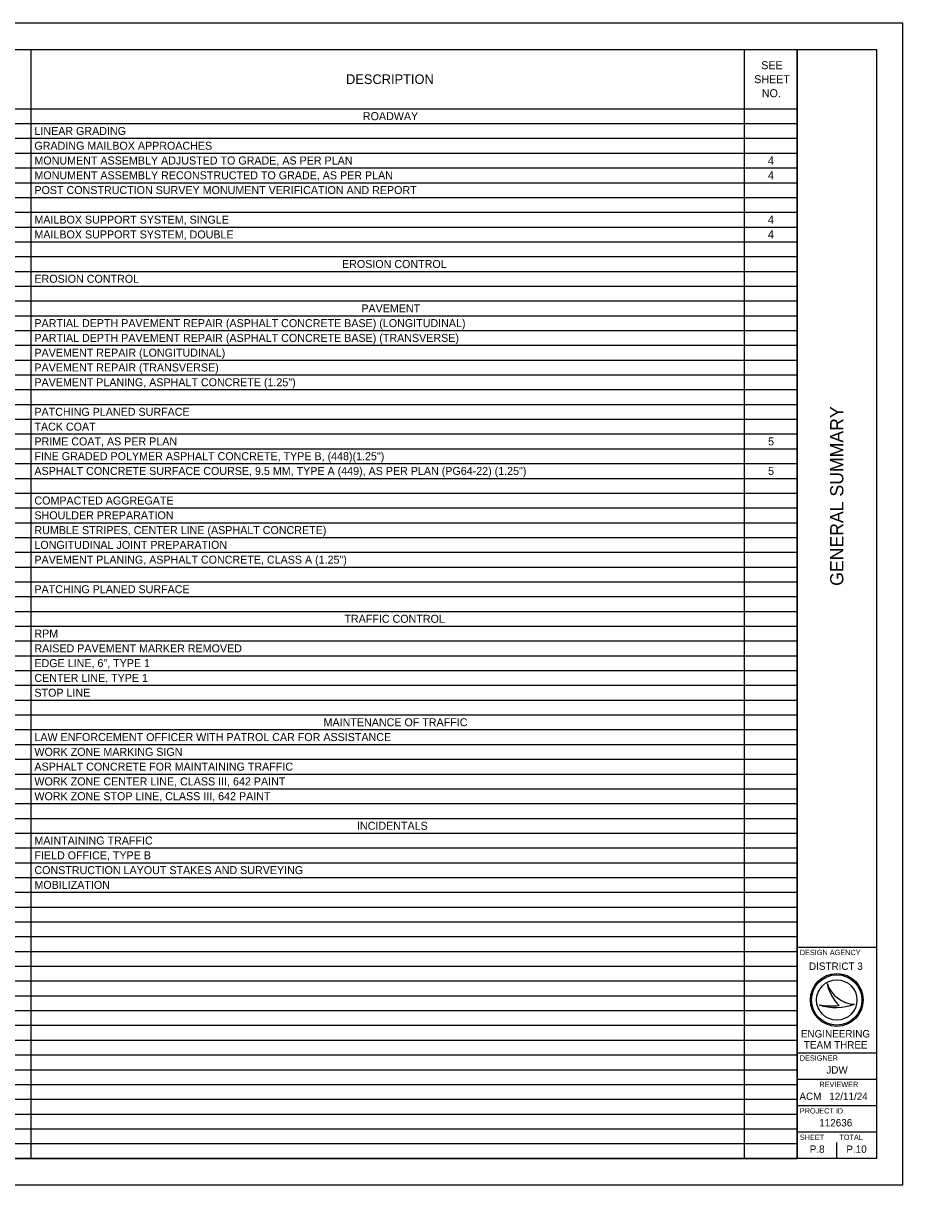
# Model space of a CAD drawing. Extents: x 0 to 34, y 0 to 22.
# Drawn here: x 17.35 to 34, y 0 to 22 of the extents above; entities that cross this region are included whole.
import ezdxf

# ---------------------------------------------------------------- set-up
doc = ezdxf.new("R2010")
doc.units = 0
for name, color, linetype in [('GM_X_County', 7, 'Continuous'), ('GM_X_Minor_Lake', 7, 'Continuous'), ('GM_X_Minor_Lake_Text', 7, 'Continuous'), ('GM_X_Minor_River_Text', 7, 'Continuous')]:
    doc.layers.add(name, color=color, linetype=linetype)

msp = doc.modelspace()

# ---------------------------------------------------------------- linework, layer by layer
at = {"layer": 'GM_X_County'}
msp.add_lwpolyline([(0, 0), (34, 0), (34, 22), (0, 22)], close=True, dxfattribs=at)
at = {"layer": 'GM_X_Minor_Lake'}
for p, q in [((1.5, 21.5), (32, 21.5)), ((17.491, 21.5), (17.491, 0.5)), ((30.995, 21.5), (30.995, 0.5)), ((32, 21.5), (32, 0.5)), ((1.5, 20.38), (32, 20.38)), ((1.5, 20.1), (32, 20.1)), ((1.5, 19.82), (32, 19.82)), ((1.5, 19.54), (32, 19.54)), ((1.5, 19.26), (32, 19.26)), ((1.5, 18.98), (32, 18.98)), ((1.5, 18.7), (32, 18.7)), ((1.5, 18.42), (32, 18.42)), ((1.5, 18.14), (32, 18.14)), ((1.5, 17.86), (32, 17.86)), ((1.5, 17.58), (32, 17.58)), ((1.5, 17.3), (32, 17.3)), ((1.5, 17.02), (32, 17.02)), ((1.5, 16.74), (32, 16.74)), ((1.5, 16.46), (32, 16.46)), ((1.5, 16.18), (32, 16.18)), ((1.5, 15.9), (32, 15.9)), ((1.5, 15.62), (32, 15.62)), ((1.5, 15.34), (32, 15.34)), ((1.5, 15.06), (32, 15.06)), ((1.5, 14.78), (32, 14.78)), ((1.5, 14.5), (32, 14.5)), ((1.5, 14.22), (32, 14.22)), ((1.5, 13.94), (32, 13.94)), ((1.5, 13.66), (32, 13.66)), ((1.5, 13.38), (32, 13.38)), ((1.5, 13.1), (32, 13.1)), ((1.5, 12.82), (32, 12.82)), ((1.5, 12.54), (32, 12.54)), ((1.5, 12.26), (32, 12.26)), ((1.5, 11.98), (32, 11.98)), ((1.5, 11.7), (32, 11.7)), ((1.5, 11.42), (32, 11.42)), ((1.5, 11.14), (32, 11.14)), ((1.5, 10.86), (32, 10.86)), ((1.5, 10.58), (32, 10.58)), ((1.5, 10.3), (32, 10.3)), ((1.5, 10.02), (32, 10.02)), ((1.5, 9.74), (32, 9.74)), ((1.5, 9.46), (32, 9.46)), ((1.5, 9.18), (32, 9.18)), ((1.5, 8.9), (32, 8.9)), ((1.5, 8.62), (32, 8.62)), ((1.5, 8.34), (32, 8.34)), ((1.5, 8.06), (32, 8.06)), ((1.5, 7.78), (32, 7.78)), ((1.5, 7.5), (32, 7.5)), ((1.5, 7.22), (32, 7.22)), ((1.5, 6.94), (32, 6.94)), ((1.5, 6.66), (32, 6.66)), ((1.5, 6.38), (32, 6.38)), ((1.5, 6.1), (32, 6.1)), ((1.5, 5.82), (32, 5.82)), ((1.5, 5.54), (32, 5.54)), ((1.5, 5.26), (32, 5.26)), ((1.5, 4.98), (32, 4.98)), ((1.5, 4.7), (32, 4.7)), ((1.5, 4.42), (32, 4.42)), ((1.5, 4.14), (32, 4.14)), ((1.5, 3.86), (32, 3.86)), ((1.5, 3.58), (32, 3.58)), ((1.5, 3.3), (32, 3.3)), ((1.5, 3.02), (32, 3.02)), ((1.5, 2.74), (32, 2.74)), ((1.5, 2.46), (32, 2.46)), ((1.5, 2.18), (32, 2.18)), ((1.5, 1.9), (32, 1.9)), ((1.5, 1.62), (32, 1.62)), ((1.5, 1.34), (32, 1.34)), ((1.5, 1.06), (32, 1.06)), ((1.5, 0.78), (32, 0.78)), ((1.5, 0.5), (32, 0.5))]:
    msp.add_line(p, q, dxfattribs=at)
at = {"layer": 'GM_X_Minor_Lake_Text'}
for p, q in [((32.567, 3.81), (32.567, 3.81)), ((32.417, 3.41), (32.417, 3.41)), ((32.75, 3.5), (32.75, 3.5)), ((33.087, 3.419), (33.087, 3.419)), ((32.375, 0.675), (32.375, 0.675)), ((32.75, 0.5), (32.75, 0.8))]:
    msp.add_line(p, q, dxfattribs=at)
for radius in [0.5, 0.477, 0.477, 0.382]:
    msp.add_circle((32.75, 3.5), radius, dxfattribs=at)
for centre, radius, start, end in [((33.116, 3.998), 0.58, 198.9257, 198.9319), ((33.347, 3.97), 0.796, 191.6379, 191.6421), ((33.116, 3.998), 0.58, 198.9319, 267.1657), ((33.347, 3.97), 0.796, 191.6421, 226.0947), ((32.739, 4.37), 1.013, 251.4576, 290.0832), ((32.648, 4.654), 1.266, 259.4964, 259.4995), ((32.739, 4.37), 1.013, 251.4527, 251.4576), ((32.648, 4.654), 1.266, 259.4995, 276.6672)]:
    msp.add_arc(centre, radius, start, end, dxfattribs=at)
at = {"layer": 'GM_X_Minor_River_Text'}
for p, q in [((32, 0.5), (32, 21.5)), ((32, 4.5), (33.5, 4.5)), ((32, 2.5), (33.5, 2.5)), ((32, 2), (33.5, 2)), ((32, 1.5), (33.5, 1.5)), ((32, 1), (33.5, 1))]:
    msp.add_line(p, q, dxfattribs=at)
msp.add_lwpolyline([(1.5, 21.5), (33.5, 21.5), (33.5, 0.5), (1.5, 0.5)], close=True, dxfattribs=at)

# ---------------------------------------------------------------- texts
at = {"layer": 'GM_X_Minor_Lake'}
for s, height, p in [('SEE ', 0.1515, (31.32, 21.129)), ('DESCRIPTION', 0.18184, (23.458, 20.849)), ('SHEET ', 0.1515, (31.187, 20.864)), ('NO.', 0.1515, (31.331, 20.599)), ('ROADWAY', 0.1515, (23.777, 20.164)), ('LINEAR GRADING', 0.15153, (17.557, 19.884)), ('GRADING MAILBOX APPROACHES', 0.15153, (17.557, 19.604)), ('MONUMENT ASSEMBLY ADJUSTED TO GRADE, AS PER PLAN', 0.15153, (17.557, 19.324)), ('4', 0.152, (31.446, 19.324)), ('MONUMENT ASSEMBLY RECONSTRUCTED TO GRADE, AS PER PLAN', 0.15153, (17.557, 19.044)), ('4', 0.152, (31.446, 19.044)), ('POST CONSTRUCTION SURVEY MONUMENT VERIFICATION AND REPORT', 0.15153, (17.557, 18.764)), ('MAILBOX SUPPORT SYSTEM, SINGLE', 0.15153, (17.557, 18.204)), ('4', 0.152, (31.446, 18.204)), ('MAILBOX SUPPORT SYSTEM, DOUBLE', 0.15153, (17.557, 17.924)), ('4', 0.152, (31.446, 17.924)), ('EROSION CONTROL', 0.15153, (23.382, 17.364)), ('EROSION CONTROL', 0.15153, (17.557, 17.084)), ('PAVEMENT', 0.1515, (23.748, 16.524)), ('PARTIAL DEPTH PAVEMENT REPAIR (ASPHALT CONCRETE BASE) (LONGITUDINAL)', 0.15153, (17.557, 16.244)), ('PARTIAL DEPTH PAVEMENT REPAIR (ASPHALT CONCRETE BASE) (TRANSVERSE)', 0.15153, (17.557, 15.964)), ('PAVEMENT REPAIR (LONGITUDINAL)', 0.15153, (17.557, 15.684)), ('PAVEMENT REPAIR (TRANSVERSE)', 0.15153, (17.557, 15.404)), ('PAVEMENT PLANING, ASPHALT CONCRETE (1.25")', 0.15153, (17.557, 15.124)), ('PATCHING PLANED SURFACE', 0.15153, (17.557, 14.564)), ('TACK COAT', 0.1515, (17.557, 14.284)), ('PRIME COAT, AS PER PLAN', 0.15153, (17.557, 14.004)), ('5', 0.152, (31.45, 14.004)), ('FINE GRADED POLYMER ASPHALT CONCRETE, TYPE B, (448)(1.25")', 0.15153, (17.557, 13.724)), ('ASPHALT CONCRETE SURFACE COURSE, 9.5 MM, TYPE A (449), AS PER PLAN (PG64-22) (1.25")', 0.15153, (17.557, 13.444)), ('5', 0.152, (31.45, 13.444)), ('COMPACTED AGGREGATE', 0.15153, (17.557, 12.884)), ('SHOULDER PREPARATION', 0.15153, (17.557, 12.604)), ('RUMBLE STRIPES, CENTER LINE (ASPHALT CONCRETE)', 0.15153, (17.557, 12.324)), ('LONGITUDINAL JOINT PREPARATION', 0.15153, (17.557, 12.044)), ('PAVEMENT PLANING, ASPHALT CONCRETE, CLASS A (1.25")', 0.15153, (17.557, 11.764)), ('PATCHING PLANED SURFACE', 0.15153, (17.557, 11.204)), ('TRAFFIC CONTROL', 0.15153, (23.427, 10.644)), ('RPM', 0.1515, (17.557, 10.364)), ('RAISED PAVEMENT MARKER REMOVED', 0.15153, (17.557, 10.084)), ('EDGE LINE, 6", TYPE 1', 0.15153, (17.557, 9.804)), ('CENTER LINE, TYPE 1', 0.15153, (17.557, 9.524)), ('STOP LINE', 0.1515, (17.557, 9.244)), ('MAINTENANCE OF TRAFFIC', 0.15153, (23.033, 8.684)), ('LAW ENFORCEMENT OFFICER WITH PATROL CAR FOR ASSISTANCE', 0.15153, (17.557, 8.404)), ('WORK ZONE MARKING SIGN', 0.15153, (17.557, 8.124)), ('ASPHALT CONCRETE FOR MAINTAINING TRAFFIC', 0.15153, (17.557, 7.844)), ('WORK ZONE CENTER LINE, CLASS III, 642 PAINT', 0.15153, (17.557, 7.564)), ('WORK ZONE STOP LINE, CLASS III, 642 PAINT', 0.15153, (17.557, 7.284)), ('INCIDENTALS', 0.15153, (23.665, 6.724)), ('MAINTAINING TRAFFIC', 0.15153, (17.557, 6.444)), ('FIELD OFFICE, TYPE B', 0.15153, (17.557, 6.164)), ('CONSTRUCTION LAYOUT STAKES AND SURVEYING', 0.15153, (17.557, 5.884)), ('MOBILIZATION', 0.15153, (17.557, 5.604))]:
    msp.add_text(s, height=height, dxfattribs=at).set_placement(p)
at = {"layer": 'GM_X_Minor_Lake_Text'}
msp.add_text('GENERAL SUMMARY', height=0.25, rotation=90, dxfattribs=at).set_placement((32.875, 11.344))
for s, height, p in [('DESIGN AGENCY', 0.1, (32.05, 4.35)), ('DISTRICT 3', 0.14, (32.224, 4.07)), ('ENGINEERING', 0.14, (32.071, 2.79)), ('TEAM THREE', 0.14, (32.127, 2.58)), ('DESIGNER', 0.1, (32.05, 2.35)), ('JDW', 0.14, (32.553, 2.105)), ('REVIEWER', 0.1, (32.422, 1.85)), ('ACM', 0.14, (32.043, 1.605)), ('12/11/24', 0.14, (32.608, 1.605)), ('PROJECT ID', 0.1, (32.05, 1.35)), ('112636', 0.14, (32.419, 1.105)), ('SHEET', 0.1, (32.05, 0.85)), ('TOTAL', 0.1, (32.8, 0.85)), ('P.8', 0.14, (32.239, 0.605)), ('P.10', 0.14, (32.932, 0.605))]:
    msp.add_text(s, height=height, dxfattribs=at).set_placement(p)

doc.saveas('drawing.dxf')
